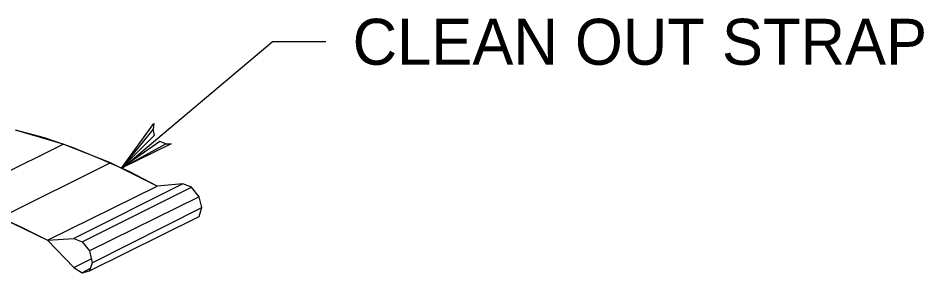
# Model space of a CAD drawing. Extents: x 636183 to 639890, y 299162 to 300538.
# Drawn here: x 636369.7 to 636428.7, y 299199.5 to 299216.1 of the extents above; entities that cross this region are included whole.
import ezdxf

# ---------------------------------------------------------------- set-up
doc = ezdxf.new("R2010")
doc.units = 0
doc.layers.add('Default', color=7, linetype='Continuous')

msp = doc.modelspace()

# ---------------------------------------------------------------- linework, layer by layer
at = {"layer": 'Default'}
for p, q in [((636376.417, 299206.33), (636386.199, 299214.603)), ((636389.697, 299214.603), (636386.199, 299214.603)), ((636371.365, 299208.344), (636369.476, 299208.834)), ((636372.589, 299207.925), (636369.476, 299208.834)), ((636365.489, 299204.392), (636372.589, 299207.925)), ((636373.184, 299207.715), (636371.365, 299208.344)), ((636375.667, 299206.701), (636372.589, 299207.925)), ((636375.038, 299206.945), (636373.184, 299207.715)), ((636376.891, 299206.141), (636375.038, 299206.945)), ((636375.667, 299206.701), (636368.532, 299203.133)), ((636378.71, 299205.197), (636375.667, 299206.701)), ((636378.71, 299205.197), (636376.891, 299206.141)), ((636371.575, 299201.664), (636378.71, 299205.197)), ((636380.389, 299205.336), (636373.289, 299201.769)), ((636373.813, 299201.559), (636380.949, 299205.127)), ((636380.389, 299205.336), (636378.71, 299205.197)), ((636380.949, 299205.127), (636380.389, 299205.336)), ((636381.438, 299204.497), (636380.949, 299205.127)), ((636381.438, 299204.497), (636374.303, 299200.964)), ((636381.613, 299203.798), (636381.438, 299204.497)), ((636374.478, 299200.195), (636381.613, 299203.798)), ((636381.438, 299203.203), (636381.613, 299203.798)), ((636368.042, 299203.343), (636369.826, 299202.538)), ((636374.303, 299199.67), (636381.438, 299203.203)), ((636368.532, 299203.133), (636371.575, 299201.664)), ((636369.826, 299202.538), (636371.575, 299201.664)), ((636371.575, 299201.664), (636373.289, 299201.769)), ((636371.575, 299201.664), (636373.289, 299199.88)), ((636373.289, 299201.769), (636373.813, 299201.559)), ((636373.813, 299201.559), (636374.303, 299200.964)), ((636374.303, 299200.964), (636374.478, 299200.195)), ((636373.289, 299199.88), (636374.408, 299200.44)), ((636374.408, 299200.44), (636374.478, 299200.195)), ((636373.289, 299199.88), (636373.813, 299199.53)), ((636374.338, 299199.81), (636373.813, 299199.53)), ((636373.813, 299199.53), (636374.303, 299199.67)), ((636374.478, 299200.195), (636374.303, 299199.67)), ((636374.303, 299199.67), (636374.338, 299199.81))]:
    msp.add_line(p, q, dxfattribs=at)
msp.add_lwpolyline([(636379.275, 299207.947), (636379.624, 299207.949), (636376.391, 299206.354), (636379.275, 299207.947), (636378.884, 299208.106), (636376.391, 299206.354), (636378.543, 299208.503), (636378.441, 299208.907), (636376.391, 299206.354), (636378.494, 299209.283), (636378.441, 299208.907)], dxfattribs=at)

# ---------------------------------------------------------------- texts
msp.add_text('CLEAN OUT STRAP', height=2.99804, dxfattribs=at).set_placement((636391.445, 299213.104))

doc.saveas('drawing.dxf')
